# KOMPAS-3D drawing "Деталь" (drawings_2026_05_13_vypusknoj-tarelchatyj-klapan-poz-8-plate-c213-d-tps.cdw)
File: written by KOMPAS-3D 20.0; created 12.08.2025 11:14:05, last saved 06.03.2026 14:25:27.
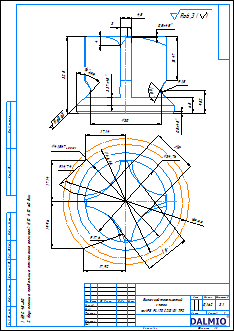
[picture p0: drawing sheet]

Sheet 1: A3, portrait

Document properties: Автор: VLAD; Знак неуказанной шероховатости: 5; Параметр неуказанной шероховатости: Ra6,3; Масса: 0.162; Полное имя файла: Выпускной тарельчатый клапан.m3d

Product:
- Part/product: Деталь
    Масса: 0.162772

Title block, sheet 1: Наименование: Выпускной тарельчатый / клапан / поз.№8, PLATE C213 (D) TPS; Масса: 0,162; Количество листов документа: 1; Форматы листов документа: A3; stored path: C:\Users\VLAD\Desktop\Выпускной тарельчатый клапан  поз.№8, PLATE C213 (D) TPS.cdw

Views: Вид 1, Проекционный вид 2
Referenced files in D:\Библиотека\: Логотип.jpg
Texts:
  Ra0,63
  1. HRC 48-50
  2. Неуказанные предельные отклонения размеров Н10, h10, ±0,5мм
  Ra6,3
  Ra6,3 ( )
Dimensions and other numbers on the sheet: 18,47; 0,5; 6,5; 9,52; 3,37; 30; 4; 4,8; 3; 1,5; 32,5; 105; 41,5; 14,74; 34,76; 17,6; 17,92; 19,96; 19; 17,14; 48,48; 53,65; 3:1; 1; 0,162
